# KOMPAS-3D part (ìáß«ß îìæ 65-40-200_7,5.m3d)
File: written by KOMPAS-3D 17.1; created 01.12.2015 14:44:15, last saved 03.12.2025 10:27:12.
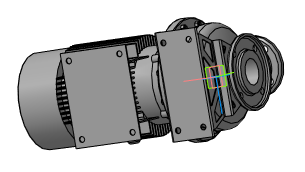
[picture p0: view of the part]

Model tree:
1. Операция без истории:3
